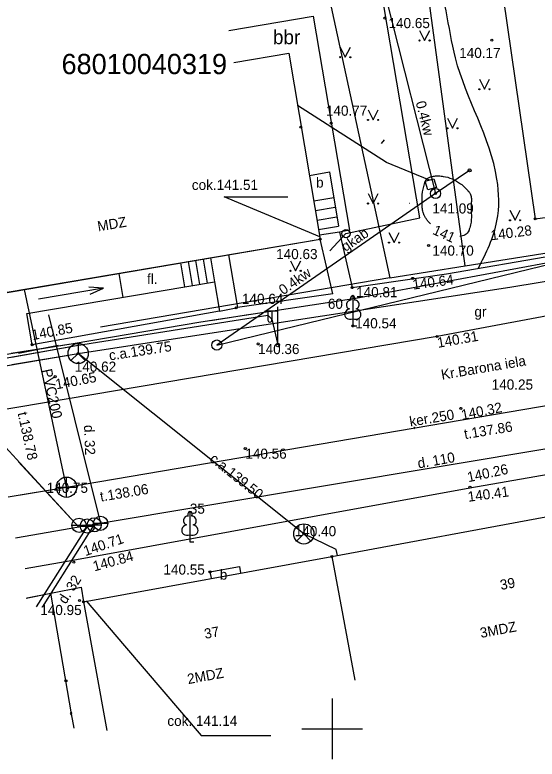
# Model space of a CAD drawing. Extents: x 728848 to 728956, y 273098 to 273185.
# Drawn here: x 728884.32 to 728910.13, y 273098.5 to 273135.25 of the extents above; entities that cross this region are included whole.
import ezdxf

# ---------------------------------------------------------------- set-up
doc = ezdxf.new("R2010")
doc.units = 0
for name, color, linetype in [('APGS_ACRL_####_####_#', 7, 'Continuous'), ('APGS_ELEM_####_####_#', 7, 'Continuous'), ('APGS_VADP_ZSPR_####_I', 7, 'Continuous'), ('BUVE_BDET_####_####_#', 7, 'Continuous'), ('BUVE_BDET_####_TKST_#', 7, 'Continuous'), ('BUVE_EKAS_####_####_#', 7, 'Continuous'), ('BUVE_EKAS_ADRS_TKST_#', 7, 'Continuous'), ('BUVE_EKAS_RAKS_TKST_#', 7, 'Continuous'), ('CELI_CAPM_####_####_#', 7, 'Continuous'), ('CELI_CMAL_####_####_#', 7, 'Continuous'), ('CELI_CSEG_####_TKST_#', 7, 'Continuous'), ('CELI_IELA_####_TKST_#', 7, 'Continuous'), ('CELI_SEGL_####_####_#', 7, 'Continuous'), ('ELEK_ACRL_####_####_#', 7, 'Continuous'), ('ELEK_ELEM_####_####_#', 7, 'Continuous'), ('ELEK_SAIT_####_####_#', 7, 'Continuous'), ('ELEK_SAVL_####_####_#', 7, 'Continuous'), ('ELEK_VADP_ZSPR_####_#', 7, 'Continuous'), ('ELEK_VADP_ZSPR_####_I', 7, 'Continuous'), ('ELEK_VADV_ZSPR_####_#', 7, 'Continuous'), ('ELEK_VADV_ZSPR_TKST_#', 7, 'Continuous'), ('GEOD_ELEM_####_####_#', 7, 'Continuous'), ('Level 1', 7, 'Continuous'), ('Level 23', 7, 'Continuous'), ('NORB_ELEM_####_####_#', 7, 'Continuous'), ('NORB_ZOGS_ZSTP_####_#', 7, 'Continuous'), ('RELJ_AATZ_####_TKST_#', 7, 'Continuous'), ('RELJ_ELEM_####_####_#', 7, 'Continuous'), ('RELJ_HORZ_####_TKST_#', 7, 'Continuous'), ('RELJ_HORZ_PAMT_####_#', 7, 'Continuous'), ('ROBZ_KADS_####_TKST_#', 7, 'Continuous'), ('ROBZ_UZMR_####_####_#', 7, 'Continuous'), ('SAKK_ELEM_####_####_#', 7, 'Continuous'), ('SAKK_ELEM_####_TKST_#', 7, 'Continuous'), ('SAKK_KKAN_####_####_#', 7, 'Continuous'), ('SAKK_KKAN_####_TKST_#', 7, 'Continuous'), ('SKAN_ELEM_####_####_#', 7, 'Continuous'), ('SKAN_VADP_PAST_####_#', 7, 'Continuous'), ('SKAN_VADP_PAST_TKST_#', 7, 'Continuous'), ('TERT_ELEM_####_####_#', 7, 'Continuous'), ('UDTK_ELEM_####_####_#', 7, 'Continuous'), ('UDTK_VADP_UDEN_####_#', 7, 'Continuous'), ('UDTK_VADP_UDEN_TKST_#', 7, 'Continuous')]:
    doc.layers.add(name, color=color, linetype=linetype)

msp = doc.modelspace()

# ---------------------------------------------------------------- linework, layer by layer
at = {"layer": 'APGS_ACRL_####_####_#'}
for points in [[(728882.8, 273118.116), (728887.366, 273118.92), (728896.816, 273120.42), (728897.026, 273120.224), (728897.316, 273118.953)], [(728884.152, 273118.354), (728887.366, 273118.92), (728896.816, 273120.42), (728897.026, 273120.224), (728897.316, 273118.953)]]:
    msp.add_lwpolyline(points, dxfattribs=at)
at = {"layer": 'APGS_ELEM_####_####_#'}
for p, q in [((728897.316, 273120.62), (728896.681, 273120.615)), ((728896.816, 273120.616), (728896.816, 273120.224)), ((728897.026, 273120.618), (728897.026, 273120.224)), ((728897.316, 273118.953), (728897.316, 273120.836))]:
    msp.add_line(p, q, dxfattribs=at)
msp.add_circle((728897.316, 273118.953), 0.09, dxfattribs=at)
msp.add_ellipse((728896.921, 273120.224), major_axis=(0, 0.151), ratio=0.695971, start_param=1.570796, end_param=4.712389, dxfattribs=at)
at = {"layer": 'APGS_VADP_ZSPR_####_I'}
for points in [[(728882.8, 273118.118), (728887.366, 273118.92), (728896.816, 273120.42), (728897.026, 273120.224), (728897.316, 273118.953)], [(728884.152, 273118.355), (728887.366, 273118.92), (728896.816, 273120.42), (728897.026, 273120.224), (728897.316, 273118.953)]]:
    msp.add_lwpolyline(points, dxfattribs=at)
at = {"layer": 'BUVE_BDET_####_####_#'}
for p, q in [((728898.877, 273127.33), (728899.863, 273127.497)), ((728899.863, 273127.497), (728900.317, 273124.815)), ((728899.091, 273126.068), (728900.077, 273126.235)), ((728899.171, 273125.594), (728900.157, 273125.761)), ((728899.252, 273125.121), (728900.237, 273125.288)), ((728899.332, 273124.648), (728900.317, 273124.815)), ((728892.88, 273123.068), (728893.08, 273121.884)), ((728893.249, 273123.13), (728893.45, 273121.947)), ((728893.619, 273123.193), (728893.82, 273122.01)), ((728893.989, 273123.256), (728894.189, 273122.072)), ((728894.876, 273123.406), (728895.318, 273120.801)), ((728892.51, 273123.005), (728892.71, 273121.822)), ((728889.454, 273122.487), (728889.654, 273121.304)), ((728884.909, 273120.5), (728894.189, 273122.072)), ((728894.189, 273122.072), (728894.435, 273120.621)), ((728888.696, 273121.757), (728885.493, 273121.218)), ((728885.17, 273118.966), (728884.909, 273120.5)), ((728894.435, 273120.621), (728895.258, 273120.792)), ((728893.963, 273107.751), (728895.417, 273108.014)), ((728895.417, 273108.014), (728895.475, 273107.693)), ((728893.963, 273107.751), (728894.021, 273107.43))]:
    msp.add_line(p, q, dxfattribs=at)
for points in [[(728899.397, 273124.295), (728894.66, 273126.274), (728897.803, 273126.274)], [(728888.035, 273121.468), (728888.696, 273121.757), (728887.977, 273121.813)], [(728887.835, 273106.309), (728889.733, 273104.097)], [(728889.733, 273104.097), (728893.529, 273099.671), (728896.967, 273099.671)]]:
    msp.add_lwpolyline(points, dxfattribs=at)
at = {"layer": 'BUVE_EKAS_####_####_#'}
for p, q in [((728904.348, 273164.427), (728910.037, 273125.181)), ((728895.133, 273132.903), (728897.853, 273133.364)), ((728897.853, 273133.364), (728899.412, 273124.175)), ((728910.037, 273125.181), (728928.159, 273127.726)), ((728882.332, 273121.28), (728899.412, 273124.175)), ((728883.944, 273121.553), (728899.412, 273124.175)), ((728899.988, 273108.511), (728915.742, 273111.435)), ((728887.713, 273106.266), (728899.988, 273108.511)), ((728899.988, 273108.511), (728900.529, 273105.597)), ((728887.713, 273106.266), (728888.863, 273099.921)), ((728900.529, 273105.597), (728901.124, 273102.392))]:
    msp.add_line(p, q, dxfattribs=at)
at = {"layer": 'CELI_CAPM_####_####_#'}
msp.add_lwpolyline([(728921.451, 273114.43), (728906.807, 273111.886), (728887.177, 273108.316), (728884.836, 273107.893)], dxfattribs=at)
at = {"layer": 'CELI_CMAL_####_####_#'}
for p, q in [((728894.89, 273134.484), (728899.061, 273135.191)), ((728899.061, 273135.191), (728900.854, 273124.622)), ((728905.649, 273122.465), (728927.067, 273126.15)), ((728886.101, 273106.695), (728887.595, 273106.994)), ((728887.595, 273106.994), (728887.713, 273106.266)), ((728887.245, 273100.022), (728887.123, 273100.733))]:
    msp.add_line(p, q, dxfattribs=at)
for points in [[(728940.62, 273126.01), (728905.191, 273119.377), (728883.236, 273115.671)], [(728900.854, 273124.622), (728900.356, 273124.521)], [(728900.356, 273124.521), (728899.378, 273124.376)], [(728900.032, 273121.481), (728899.412, 273124.175)], [(728900.356, 273124.521), (728900.986, 273121.784), (728905.649, 273122.465)], [(728900.032, 273121.481), (728895.318, 273120.801)], [(728894.435, 273120.621), (728885.17, 273118.966)], [(728887.123, 273100.733), (728886.101, 273106.695)]]:
    msp.add_lwpolyline(points, dxfattribs=at)
at = {"layer": 'CELI_SEGL_####_####_#'}
for p in [(728884.879, 273106.451), (728884.929, 273106.461)]:
    msp.add_line(p, (728886.101, 273106.695), dxfattribs=at)
at = {"layer": 'ELEK_ACRL_####_####_#'}
for points in [[(728893.991, 273120.166), (728895.963, 273120.468)], [(728884.495, 273118.555), (728886.46, 273118.941)]]:
    msp.add_lwpolyline(points, dxfattribs=at)
at = {"layer": 'ELEK_ELEM_####_####_#'}
msp.add_lwpolyline([(728905.156, 273126.738), (728904.726, 273126.614), (728904.604, 273127.037), (728905.034, 273127.161)], close=True, dxfattribs=at)
for centre, radius in [((728906.792, 273127.576), 0.075), ((728905.113, 273126.437), 0.25), ((728894.302, 273118.95), 0.25)]:
    msp.add_circle(centre, radius, dxfattribs=at)
at = {"layer": 'ELEK_SAIT_####_####_#'}
msp.add_line((728906.792, 273127.576), (728905.113, 273126.437), dxfattribs=at)
at = {"layer": 'ELEK_SAVL_####_####_#'}
msp.add_line((728903.83, 273125.963), (728903.838, 273125.961), dxfattribs=at)
at = {"layer": 'ELEK_VADP_ZSPR_####_#'}
for points in [[(728904.819, 273127.099), (728902.686, 273127.963), (728898.291, 273130.781)], [(728902.568, 273129.084), (728902.428, 273128.908)]]:
    msp.add_lwpolyline(points, dxfattribs=at)
at = {"layer": 'ELEK_VADP_ZSPR_####_I'}
for points in [[(728882.763, 273118.325), (728887.201, 273119.02), (728893.506, 273120.092), (728901.17, 273121.265), (728917.144, 273124.228), (728922.252, 273124.972), (728927.817, 273125.955)], [(728884.14, 273118.541), (728887.201, 273119.02), (728893.506, 273120.092), (728901.17, 273121.265), (728917.144, 273124.228), (728922.252, 273124.972), (728927.817, 273125.955)]]:
    msp.add_lwpolyline(points, dxfattribs=at)
at = {"layer": 'ELEK_VADV_ZSPR_####_#'}
for p, q in [((728899.357, 273149.053), (728905.113, 273126.437)), ((728905.113, 273126.437), (728894.302, 273118.95)), ((728894.302, 273118.95), (728921.335, 273125.511))]:
    msp.add_line(p, q, dxfattribs=at)
at = {"layer": 'GEOD_ELEM_####_####_#'}
for p, q in [((728900, 273101.5), (728900, 273100)), ((728898.5, 273100), (728900, 273100)), ((728900, 273100), (728900, 273098.5)), ((728900, 273100), (728901.5, 273100))]:
    msp.add_line(p, q, dxfattribs=at)
at = {"layer": 'Level 1'}
for p, q in [((728901.018, 273120.239), (728901.018, 273119.892)), ((728901.018, 273119.892), (728901.218, 273119.892)), ((728892.971, 273109.579), (728892.971, 273109.232)), ((728892.971, 273109.232), (728893.171, 273109.232))]:
    msp.add_line(p, q, dxfattribs=at)
for points in [[(728901.018, 273121.392), (728901.018, 273120.239)], [(728901.108, 273121.16), (728901.107, 273121.161)], [(728892.971, 273110.732), (728892.971, 273109.579)], [(728893.061, 273110.5), (728893.06, 273110.501)]]:
    msp.add_lwpolyline(points, dxfattribs=at)
for centre, major_axis, ratio, start_param, end_param in [((728901.018, 273121.242), (0, -0.15), 0.707107, 3.14537, 5.287485), ((728901.018, 273121.242), (0, -0.15), 0.707107, 0.995701, 3.137816), ((728900.89, 273120.947), (-0.039, -0.212), 0.861323, 3.141593, 6.283185), ((728901.146, 273120.947), (0.039, -0.212), 0.861323, 0, 3.141593), ((728900.928, 273120.485), (0.307, 0.095), 0.814445, 1.570796, 4.752015), ((728901.108, 273120.485), (-0.307, 0.095), 0.814445, 1.531171, 4.712389), ((728892.971, 273110.582), (0, -0.15), 0.707107, 3.14537, 5.287485), ((728892.971, 273110.582), (0, -0.15), 0.707107, 0.995701, 3.137816), ((728892.843, 273110.287), (-0.039, -0.212), 0.861323, 3.141593, 6.283185), ((728893.099, 273110.287), (0.039, -0.212), 0.861323, 0, 3.141593), ((728892.881, 273109.825), (0.307, 0.095), 0.814445, 1.570796, 4.752015), ((728893.061, 273109.825), (-0.307, 0.095), 0.814445, 1.531171, 4.712389)]:
    msp.add_ellipse(centre, major_axis=major_axis, ratio=ratio, start_param=start_param, end_param=end_param, dxfattribs=at)
at = {"layer": 'Level 23'}
for p, q in [((728897.947, 273123.116), (728898.197, 273122.616)), ((728898.197, 273122.616), (728898.447, 273123.116))]:
    msp.add_line(p, q, dxfattribs=at)
for centre, radius in [((728897.946, 273122.615), 0.028), ((728898.446, 273122.615), 0.0263)]:
    msp.add_circle(centre, radius, dxfattribs=at)
at = {"layer": 'NORB_ELEM_####_####_#'}
msp.add_line((728900.682, 273124.453), (728899.891, 273123.597), dxfattribs=at)
msp.add_circle((728900.682, 273124.453), 0.202, dxfattribs=at)
at = {"layer": 'NORB_ZOGS_ZSTP_####_#'}
for points in [[(728904.34, 273125.23), (728901.425, 273142.428)], [(728900.682, 273124.453), (728904.34, 273125.23)]]:
    msp.add_lwpolyline(points, dxfattribs=at)
at = {"layer": 'RELJ_ELEM_####_####_#'}
msp.add_line((728887.114, 273100.7), (728887.138, 273100.788), dxfattribs=at)
for centre in [(728902.599, 273135.1), (728907.894, 273134.006), (728898.456, 273129.71), (728899.957, 273129.907), (728905.113, 273126.437), (728910.037, 273125.181), (728899.412, 273124.175), (728904.769, 273123.864), (728903.979, 273122.243), (728900.986, 273121.784), (728895.258, 273120.792), (728901.018, 273119.892), (728905.191, 273119.377), (728885.17, 273118.966), (728896.34, 273119.002), (728887.446, 273118.532), (728886.316, 273117.388), (728906.356, 273115.822), (728895.709, 273113.834), (728886.93, 273111.9), (728906.813, 273111.934), (728898.599, 273109.621), (728899.988, 273108.511), (728887.233, 273108.229), (728893.963, 273107.751), (728887.509, 273106.337), (728887.713, 273106.266), (728886.844, 273102.362)]:
    msp.add_circle(centre, 0.05, dxfattribs=at)
msp.add_arc((728887.107, 273100.749), 0.05, 51.062, 277.5227, dxfattribs=at)
at = {"layer": 'RELJ_HORZ_PAMT_####_#'}
for points in [[(728907.225, 273122.736), (728908.147, 273125.08), (728908.147, 273127.137), (728906.094, 273133.127), (728904.941, 273137.666), (728903.27, 273139.609), (728900.929, 273140.747), (728896.538, 273141.6)], [(728904.46, 273126.52), (728904.604, 273127.037), (728904.615, 273127.067), (728904.631, 273127.096), (728904.674, 273127.147), (728904.793, 273127.224), (728904.933, 273127.272), (728905.002, 273127.286), (728905.034, 273127.291), (728905.065, 273127.295), (728905.168, 273127.301), (728905.274, 273127.301), (728905.489, 273127.281), (728905.925, 273127.158), (728906.352, 273126.912), (728906.555, 273126.738), (728906.654, 273126.638), (728906.702, 273126.584), (728906.725, 273126.557), (728906.737, 273126.543), (728906.749, 273126.528), (728906.786, 273126.479), (728906.816, 273126.429), (728906.857, 273126.33), (728906.886, 273126.132), (728906.875, 273125.933), (728906.868, 273125.834), (728906.866, 273125.784), (728906.867, 273125.734), (728906.879, 273125.45), (728906.879, 273125.164), (728906.844, 273124.879), (728906.806, 273124.737), (728906.78, 273124.666), (728906.765, 273124.631), (728906.757, 273124.613), (728906.749, 273124.595), (728906.569, 273124.393), (728906.308, 273124.305)], [(728904.866, 273124.929), (728904.811, 273124.984), (728904.758, 273125.042), (728904.661, 273125.163), (728904.58, 273125.295), (728904.547, 273125.365), (728904.532, 273125.402), (728904.519, 273125.439), (728904.46, 273125.672), (728904.443, 273125.907), (728904.46, 273126.52)]]:
    msp.add_spline(points, degree=3, dxfattribs=at)
at = {"layer": 'ROBZ_UZMR_####_####_#'}
for points in [[(728902.844, 273122.265), (728906.58, 273122.86), (728903.634, 273144.437), (728904.623, 273144.571), (728901.876, 273165.08), (728895.601, 273164.553)], [(728903.634, 273144.437), (728898.213, 273143.701), (728902.844, 273122.265), (728888.555, 273119.835)], [(728906.58, 273122.86), (728918.09, 273124.69)]]:
    msp.add_lwpolyline(points, dxfattribs=at)
at = {"layer": 'SAKK_ELEM_####_####_#'}
for p, q in [((728887.446, 273118.532), (728887.8, 273118.178)), ((728898.599, 273109.621), (728898.953, 273109.267))]:
    msp.add_line(p, q, dxfattribs=at)
for points in [[(728887.446, 273119.032), (728887.446, 273118.532), (728887.092, 273118.178)], [(728898.599, 273110.121), (728898.599, 273109.621), (728898.245, 273109.267)]]:
    msp.add_lwpolyline(points, dxfattribs=at)
for centre in [(728887.446, 273118.532), (728898.599, 273109.621)]:
    msp.add_circle(centre, 0.5, dxfattribs=at)
at = {"layer": 'SAKK_KKAN_####_####_#'}
for points in [[(728882.864, 273117.761), (728887.446, 273118.532), (728897.906, 273120.141), (728908.778, 273121.814), (728946.269, 273127.973)], [(728884.177, 273117.982), (728887.446, 273118.532), (728897.906, 273120.141), (728908.778, 273121.814), (728934.266, 273126.001)], [(728900.266, 273108.563), (728900.191, 273108.86), (728898.599, 273109.621), (728887.446, 273118.532)]]:
    msp.add_lwpolyline(points, dxfattribs=at)
at = {"layer": 'SKAN_ELEM_####_####_#'}
for p, q in [((728886.872, 273111.428), (728886.872, 273112.428)), ((728886.372, 273111.928), (728887.372, 273111.928))]:
    msp.add_line(p, q, dxfattribs=at)
msp.add_circle((728886.872, 273111.928), 0.5, dxfattribs=at)
at = {"layer": 'SKAN_VADP_PAST_####_#'}
for points in [[(728883.987, 273111.458), (728886.872, 273111.928), (728884.797, 273121.698)], [(728884.597, 273111.557), (728886.872, 273111.928), (728884.797, 273121.698)], [(728886.872, 273111.928), (728911.07, 273116.044), (728926.111, 273118.506), (728928.031, 273102.999)], [(728886.872, 273111.928), (728911.07, 273116.044), (728926.111, 273118.506), (728927.844, 273104.509)]]:
    msp.add_lwpolyline(points, dxfattribs=at)
at = {"layer": 'TERT_ELEM_####_####_#'}
for p, q in [((728904.32, 273134.491), (728904.57, 273133.991)), ((728904.57, 273133.991), (728904.82, 273134.491)), ((728900.399, 273133.665), (728900.649, 273133.165)), ((728900.649, 273133.165), (728900.899, 273133.665)), ((728907.277, 273132.082), (728907.527, 273131.582)), ((728907.527, 273131.582), (728907.777, 273132.082)), ((728901.775, 273130.568), (728902.025, 273130.068)), ((728902.025, 273130.068), (728902.275, 273130.568)), ((728905.695, 273130.155), (728905.945, 273129.655)), ((728905.945, 273129.655), (728906.195, 273130.155)), ((728901.775, 273126.437), (728902.025, 273125.937)), ((728902.025, 273125.937), (728902.275, 273126.437)), ((728908.79, 273125.611), (728909.04, 273125.111)), ((728909.04, 273125.111), (728909.29, 273125.611)), ((728902.81, 273124.51), (728903.06, 273124.01)), ((728903.06, 273124.01), (728903.31, 273124.51))]:
    msp.add_line(p, q, dxfattribs=at)
for centre, radius in [((728904.319, 273133.991), 0.028), ((728904.819, 273133.991), 0.0263), ((728900.399, 273133.165), 0.028), ((728900.899, 273133.165), 0.0263), ((728907.277, 273131.582), 0.028), ((728907.777, 273131.582), 0.0263), ((728901.775, 273130.067), 0.028), ((728902.275, 273130.067), 0.0263), ((728905.695, 273129.654), 0.028), ((728906.195, 273129.654), 0.0263), ((728901.775, 273125.937), 0.028), ((728902.275, 273125.937), 0.0263), ((728908.79, 273125.111), 0.028), ((728909.29, 273125.111), 0.0263), ((728902.81, 273124.009), 0.028), ((728903.31, 273124.009), 0.0263)]:
    msp.add_circle(centre, radius, dxfattribs=at)
at = {"layer": 'UDTK_ELEM_####_####_#'}
for p, q in [((728887.138, 273110.048), (728887.84, 273110.048)), ((728887.488, 273110.048), (728887.488, 273110.049)), ((728887.544, 273110.012), (728888.246, 273110.012)), ((728887.89, 273110.07), (728888.592, 273110.07)), ((728887.894, 273110.012), (728887.894, 273110.013)), ((728888.207, 273110.148), (728888.909, 273110.148)), ((728888.24, 273110.07), (728888.24, 273110.071)), ((728888.557, 273110.148), (728888.557, 273110.149))]:
    msp.add_line(p, q, dxfattribs=at)
for centre in [(728887.489, 273110.048), (728887.895, 273110.012), (728888.241, 273110.07), (728888.558, 273110.148)]:
    msp.add_circle(centre, 0.351, dxfattribs=at)
at = {"layer": 'UDTK_VADP_UDEN_####_#'}
for p, q in [((728885.983, 273120.447), (728888.559, 273110.142)), ((728923.344, 273115.945), (728888.239, 273110.085)), ((728883.481, 273114.299), (728887.486, 273109.955)), ((728884.489, 273113.205), (728887.486, 273109.955)), ((728888.239, 273110.085), (728884.352, 273109.412)), ((728888.239, 273110.085), (728884.732, 273109.478)), ((728887.904, 273110.027), (728885.366, 273106.022)), ((728885.681, 273106), (728888.252, 273110.087))]:
    msp.add_line(p, q, dxfattribs=at)

# ---------------------------------------------------------------- texts
at = {"layer": 'BUVE_BDET_####_TKST_#'}
for s, p in [('cok.141.51', (728893.066, 273126.61)), ('b', (728899.205, 273126.728)), ('fl.', (728890.85, 273121.965)), ('b', (728894.447, 273107.362)), ('cok. 141.14', (728891.856, 273100.139))]:
    msp.add_text(s, height=0.5, dxfattribs=at).set_placement(p)
at = {"layer": 'BUVE_EKAS_ADRS_TKST_#'}
for s, rotation, p in [('39', 10.515, (728908.348, 273106.849)), ('37', 10.27, (728893.724, 273104.435))]:
    msp.add_text(s, height=0.5, rotation=rotation, dxfattribs=at).set_placement(p)
at = {"layer": 'BUVE_EKAS_RAKS_TKST_#'}
for s, rotation, p in [('MDZ', 9.619, (728888.444, 273124.559)), ('3MDZ', 10.515, (728907.357, 273104.481)), ('2MDZ', 10.27, (728892.888, 273102.202))]:
    msp.add_text(s, height=0.5, rotation=rotation, dxfattribs=at).set_placement(p)
at = {"layer": 'CELI_CSEG_####_TKST_#'}
for s, height, p in [('bbr', 0.7, (728897.072, 273133.806)), ('gr', 0.5, (728907.031, 273120.35))]:
    msp.add_text(s, height=height, dxfattribs=at).set_placement(p)
at = {"layer": 'CELI_IELA_####_TKST_#'}
msp.add_text('Kr.Barona iela', height=0.5, rotation=9.664, dxfattribs=at).set_placement((728905.429, 273117.235))
at = {"layer": 'ELEK_VADV_ZSPR_TKST_#'}
for s, rotation, p in [('0.4kw', 284.278, (728904.123, 273130.934)), ('gkab', 34.704, (728900.663, 273123.538)), ('0.4kw', 34.704, (728897.581, 273121.403))]:
    msp.add_text(s, height=0.5, rotation=rotation, dxfattribs=at).set_placement(p)
at = {"layer": 'Level 1'}
for s, p in [('60', (728899.789, 273120.738)), ('35', (728892.967, 273110.619))]:
    msp.add_text(s, height=0.5, dxfattribs=at).set_placement(p)
at = {"layer": 'RELJ_AATZ_####_TKST_#'}
for s, p in [(' 140.65', (728902.599, 273134.6)), (' 140.17', (728906.094, 273133.127)), (' 140.77', (728899.506, 273130.274)), (' 141.09', (728904.769, 273125.446)), (' 140.70', (728904.769, 273123.364)), (' 140.63', (728897.047, 273123.192)), ('140.81', (728901.184, 273121.311)), ('140.64', (728895.542, 273120.981)), (' 140.54', (728900.952, 273119.775)), ('140.36', (728896.34, 273118.502)), ('140.56', (728895.709, 273113.334)), (' 140.55', (728891.476, 273107.613)), ('140.95', (728885.574, 273105.615))]:
    msp.add_text(s, height=0.5, dxfattribs=at).set_placement(p)
for s, rotation, p in [('140.28', 7.3404, (728907.871, 273124.121)), ('140.64', 7.3404, (728904.004, 273121.686)), ('140.85', 10.6908, (728885.203, 273119.19)), ('140.31', 9.9444, (728905.238, 273118.81)), ('140.65', 10.5477, (728886.373, 273116.761)), ('140.32', 11.2315, (728906.431, 273115.246)), ('140.26', 12.0402, (728906.735, 273112.173)), ('140.41', 7.6008, (728906.737, 273111.207)), ('140.71', 18.9006, (728887.807, 273108.521)), ('140.84', 15.3883, (728888.251, 273107.77))]:
    msp.add_text(s, height=0.5, rotation=rotation, dxfattribs=at).set_placement(p)
at = {"layer": 'RELJ_HORZ_####_TKST_#'}
msp.add_text('141', height=0.5, rotation=335.7733, dxfattribs=at).set_placement((728904.924, 273124.448))
at = {"layer": 'ROBZ_KADS_####_TKST_#'}
msp.add_text('68010040319', height=1, dxfattribs=at).set_placement((728886.626, 273132.329))
at = {"layer": 'SAKK_ELEM_####_TKST_#'}
for s, p in [(' 140.62', (728887.095, 273117.632)), (' 140.40', (728897.968, 273109.508))]:
    msp.add_text(s, height=0.5, dxfattribs=at).set_placement(p)
at = {"layer": 'SAKK_KKAN_####_TKST_#'}
for s, rotation, p in [('c.a.139.75', 8.7449, (728889.009, 273118.185)), ('c.a.139.50', 321.3759, (728893.902, 273113.251))]:
    msp.add_text(s, height=0.5, rotation=rotation, dxfattribs=at).set_placement(p)
at = {"layer": 'SKAN_ELEM_####_####_#'}
for s, p in [('140.25', (728907.885, 273116.749)), ('140.75', (728885.888, 273111.65))]:
    msp.add_text(s, height=0.5, dxfattribs=at).set_placement(p)
at = {"layer": 'SKAN_VADP_PAST_TKST_#'}
for s, rotation, p in [('PVC200', 282.316, (728885.653, 273117.715)), ('ķer.250', 9.467, (728903.865, 273114.919)), ('t.138.78', 282.316, (728884.45, 273115.586)), ('t.137.86', 9.41, (728906.564, 273114.298)), ('t.138.06', 9.41, (728888.57, 273111.214))]:
    msp.add_text(s, height=0.5, rotation=rotation, dxfattribs=at).set_placement(p)
at = {"layer": 'UDTK_VADP_UDEN_TKST_#'}
for s, rotation, p in [('d. 32', 272.3563, (728887.733, 273114.994)), ('d. 110', 10.0818, (728904.269, 273112.851)), ('d. 32', 57.6331, (728886.833, 273106.124))]:
    msp.add_text(s, height=0.5, rotation=rotation, dxfattribs=at).set_placement(p)

doc.saveas('drawing.dxf')
